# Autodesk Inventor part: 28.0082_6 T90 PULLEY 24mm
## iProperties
Created: 2006-12
Document SubType Name: Modeling
Designer: Andy Moles
Part Number: 28.0082_6 T90 PULLEY 24mm
Material: Aluminum-6061
Density: 2.71 g/cm^3
Author: Andy Moles
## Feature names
1. Extrusion1
2. Extrusion3
3. Extrusion4
4. Extrusion6
5. Mirror1
6. Extrusion7
7. Chamfer1
